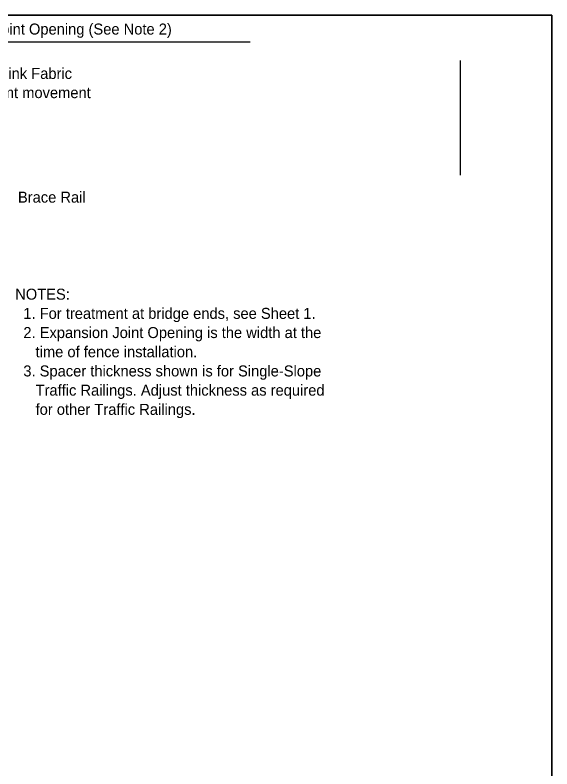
# Model space of a CAD drawing. Extents: x 0 to 41.2, y 0 to 26.
# Drawn here: x 31.36 to 41.21, y 12.14 to 25.96 of the extents above; entities that cross this region are included whole.
import ezdxf

# ---------------------------------------------------------------- set-up
doc = ezdxf.new("R2010")
doc.units = 0
for name, color, linetype in [('ActivePts-ConstElements', 7, 'Continuous'), ('Dimension', 7, 'Continuous'), ('Miscellaneous', 7, 'Continuous'), ('Miscellaneous1', 7, 'Continuous'), ('TextStructures', 7, 'Continuous')]:
    doc.layers.add(name, color=color, linetype=linetype)

msp = doc.modelspace()

# ---------------------------------------------------------------- linework, layer by layer
at = {"layer": 'ActivePts-ConstElements'}
msp.add_lwpolyline([(0, 0), (41.211, 0), (41.211, 25.96), (0, 25.96)], close=True, dxfattribs=at)
at = {"layer": 'Dimension'}
msp.add_line((25.661, 25.468), (35.673, 25.468), dxfattribs=at)
at = {"layer": 'Miscellaneous'}
msp.add_line((39.535, 23.024), (39.535, 25.124), dxfattribs=at)
at = {"layer": 'Miscellaneous1'}
msp.add_lwpolyline([(0, 25.96), (41.211, 25.96), (41.211, 0), (0, 0)], close=True, dxfattribs=at)

# ---------------------------------------------------------------- texts
at = {"layer": 'Dimension'}
for s, p in [('Bulge Chain Link Fabric', (29.539, 24.789)), ('to allow for joint movement', (29.539, 24.437)), ('NOTES:', (31.358, 20.741)), ('  1. For treatment at bridge ends, see Sheet 1.', (31.358, 20.389)), ('  2. Expansion Joint Opening is the width at the', (31.358, 20.037)), ('     time of fence installation.', (31.358, 19.685)), ('  3. Spacer thickness shown is for Single-Slope', (31.358, 19.333)), ('     Traffic Railings. Adjust thickness as required', (31.358, 18.981)), ('     for other Traffic Railings.', (31.358, 18.629))]:
    msp.add_text(s, height=0.2016, dxfattribs=at).set_placement(p)
at = {"layer": 'TextStructures'}
for s, p in [('3\'-0" + Expansion Joint Opening (See Note 2)', (28.788, 25.603)), ('Brace Rail', (31.409, 22.52))]:
    msp.add_text(s, height=0.2016, dxfattribs=at).set_placement(p)

doc.saveas('drawing.dxf')
